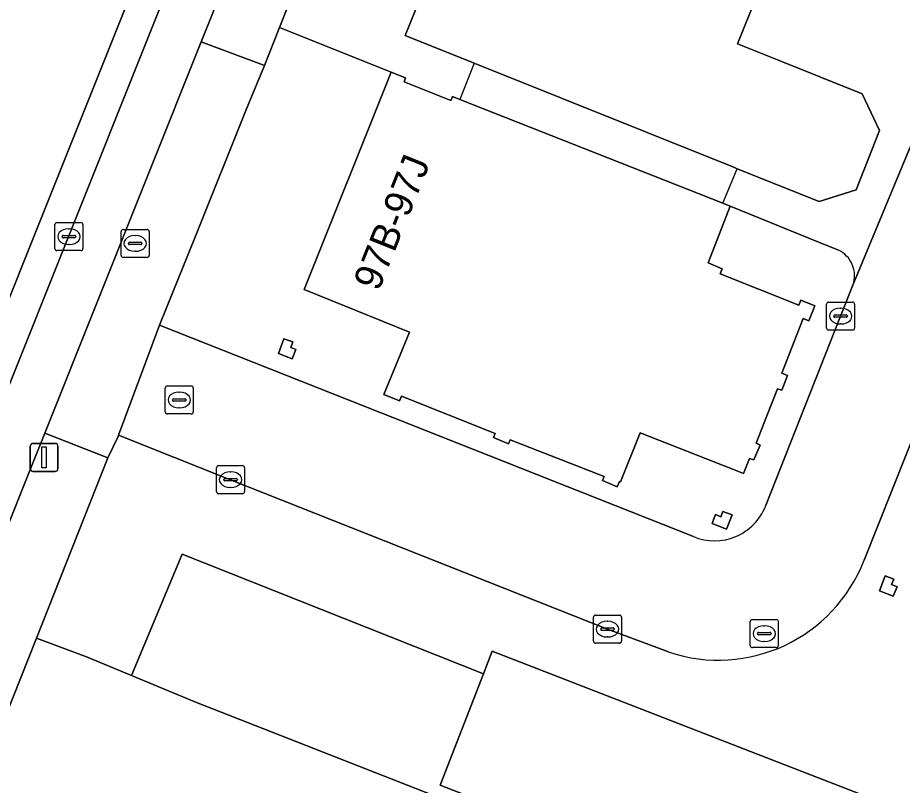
# Model space of a CAD drawing. Extents: x 160023 to 161302, y 384750 to 385707.
# Drawn here: x 160406.94 to 160438.47, y 384923.61 to 384950.96 of the extents above; entities that cross this region are included whole.
import ezdxf

# ---------------------------------------------------------------- set-up
doc = ezdxf.new("R2010")
doc.units = 0
for name, color, linetype in [('IMGEO_Brandkraan', 7, 'Continuous'), ('IMGEO_Erf', 7, 'Continuous'), ('IMGEO_Groenvoorziening', 7, 'Continuous'), ('IMGEO_Kolk', 7, 'Continuous'), ('IMGEO_Lichtmast', 7, 'Continuous'), ('IMGEO_Pand', 7, 'Continuous'), ('IMGEO_Pand_nummerreeks', 7, 'Continuous'), ('IMGEO_Pand_overbouw', 7, 'Continuous'), ('IMGEO_Parkeervlak_open', 7, 'Continuous'), ('IMGEO_Rijbaan_lokaal_open', 7, 'Continuous'), ('IMGEO_Rioolput', 7, 'Continuous'), ('IMGEO_Voetpad_open', 7, 'Continuous')]:
    doc.layers.add(name, color=color, linetype=linetype)

msp = doc.modelspace()

# ---------------------------------------------------------------- linework, layer by layer
at = {"layer": 'IMGEO_Brandkraan'}
for p, q in [((160410.7, 384943.415), (160411.552, 384943.415)), ((160410.625, 384942.489), (160410.625, 384943.341)), ((160411.113, 384943.195), (160411.138, 384943.195)), ((160411.626, 384943.341), (160411.626, 384942.489)), ((160410.884, 384942.909), (160410.884, 384942.921)), ((160411.322, 384942.872), (160410.924, 384942.872)), ((160410.927, 384942.958), (160411.325, 384942.958)), ((160411.368, 384942.921), (160411.368, 384942.909)), ((160411.136, 384942.635), (160411.111, 384942.635)), ((160411.552, 384942.415), (160410.7, 384942.415))]:
    msp.add_line(p, q, dxfattribs=at)
for points in [[(160410.7, 384943.415), (160411.552, 384943.415)], [(160410.625, 384942.489), (160410.625, 384943.341)], [(160411.626, 384943.341), (160411.626, 384942.489)], [(160411.552, 384942.415), (160410.7, 384942.415)]]:
    msp.add_lwpolyline(points, dxfattribs=at)
for centre, radius, start, end in [((160410.702, 384943.339), 0.0765, 91.552, 178.448), ((160410.702, 384943.339), 0.0765, 91.552, 178.448), ((160411.55, 384943.339), 0.0765, 1.552, 88.448), ((160411.55, 384943.339), 0.0765, 1.552, 88.448), ((160410.924, 384942.918), 0.0403, 85.8775, 175.7526), ((160410.921, 384942.908), 0.0366, 178.938, 274.7102), ((160411.325, 384942.915), 0.043, 264.8664, 352.4533), ((160411.329, 384942.92), 0.0386, 1.7309, 96.639), ((160410.702, 384942.491), 0.0765, 181.552, 268.448), ((160410.702, 384942.491), 0.0765, 181.552, 268.448), ((160411.55, 384942.491), 0.0765, 271.552, 358.448), ((160411.55, 384942.491), 0.0765, 271.552, 358.448)]:
    msp.add_arc(centre, radius, start, end, dxfattribs=at)
for centre, major_axis, ratio, start_param, end_param in [((160411.112, 384942.915), (-0.387, 0.002), 0.722429, 4.712389, 7.853982), ((160411.137, 384942.915), (-0.39, 0.002), 0.717154, 1.570796, 4.712389)]:
    msp.add_ellipse(centre, major_axis=major_axis, ratio=ratio, start_param=start_param, end_param=end_param, dxfattribs=at)
at = {"layer": 'IMGEO_Erf'}
for points in [[(160458.726, 385056.493), (160441.331, 385013.476), (160438.559, 385006.481), (160435.95, 385000), (160433.025, 384992.731), (160431.128, 384987.859), (160426.923, 384977.317), (160416.629, 384951.506), (160416.272, 384950.612), (160420.254, 384949.022), (160420.765, 384948.818), (160420.709, 384948.678), (160422.38, 384948.009), (160422.436, 384948.148), (160422.695, 384948.044), (160432.074, 384944.348), (160432.335, 384944.246), (160435.835, 384942.822), (160436.171, 384942.686)], [(160436.706, 384941.424), (160440.25, 384949.977), (160441.262, 384952.523), (160445.036, 384951.023), (160445.638, 384950.784), (160446.817, 384953.749), (160447.923, 384956.534), (160449.032, 384959.325), (160450.141, 384962.114), (160451.224, 384964.839), (160452.307, 384967.562), (160454.73, 384973.66), (160460.672, 384972.123)], [(160433.72, 384952.825), (160432.596, 384950.023), (160434.018, 384949.453), (160437.039, 384948.242), (160437.65, 384946.942), (160436.826, 384944.822), (160435.502, 384944.407), (160432.582, 384945.577), (160432.481, 384945.618), (160423.213, 384949.334), (160420.753, 384950.32), (160421.129, 384951.258)]]:
    msp.add_lwpolyline(points, dxfattribs=at)
msp.add_arc((160435.751, 384941.763), 1.014, 340.4385, 65.5086, dxfattribs=at)
at = {"layer": 'IMGEO_Groenvoorziening'}
for points in [[(160420.254, 384949.022), (160416.272, 384950.612), (160415.733, 384949.26), (160415.154, 384947.855), (160415.072, 384947.651), (160413.273, 384943.178), (160412.245, 384940.619), (160411.995, 384939.997), (160431.023, 384932.47)], [(160436.171, 384942.686), (160435.835, 384942.822), (160432.335, 384944.246), (160431.544, 384942.219), (160432.044, 384942.01), (160431.981, 384941.837), (160434.778, 384940.719), (160434.851, 384940.897), (160435.344, 384940.695), (160435.137, 384940.159), (160434.938, 384940.244), (160434.426, 384938.934), (160434.176, 384938.288), (160434.374, 384938.214), (160434.168, 384937.681), (160434.02, 384937.733), (160433.638, 384936.772), (160433.253, 384935.796), (160433.395, 384935.73), (160433.177, 384935.202), (160433.022, 384935.253), (160432.808, 384934.714), (160432.449, 384934.856), (160429.128, 384936.17), (160428.423, 384934.418), (160428.393, 384934.429), (160428.31, 384934.246), (160427.778, 384934.462), (160427.838, 384934.611), (160424.491, 384935.921), (160424.427, 384935.774), (160423.891, 384935.995), (160423.951, 384936.143), (160420.616, 384937.475), (160420.543, 384937.304), (160419.988, 384937.532), (160420.901, 384939.752), (160417.15, 384941.279), (160420.254, 384949.022)], [(160442.437, 384945.142), (160440.178, 384939.33), (160437.102, 384931.63)], [(160433.589, 384933.547), (160436.267, 384940.325), (160436.706, 384941.424)], [(160430.132, 384928.359), (160427.959, 384929.171), (160414.526, 384934.496), (160410.538, 384936.086), (160410.52, 384936.037), (160410.154, 384935.27), (160407.607, 384928.852), (160409.395, 384928.189), (160411, 384927.518), (160412.807, 384931.842), (160423.538, 384927.577), (160423.855, 384928.392), (160434.063, 384924.423), (160439.671, 384922.243), (160439.312, 384921.321), (160442.044, 384920.242), (160468.993, 384909.67)]]:
    msp.add_lwpolyline(points, dxfattribs=at)
for points in [[(160416.749, 384939.405), (160416.676, 384939.211), (160416.857, 384939.14), (160416.721, 384938.807), (160416.235, 384938.998), (160416.419, 384939.519)], [(160431.997, 384933.176), (160432.071, 384933.362), (160432.4, 384933.243), (160432.197, 384932.731), (160431.686, 384932.934), (160431.811, 384933.25)], [(160438.138, 384930.34), (160437.649, 384930.535), (160437.85, 384931.068), (160438.162, 384930.953), (160438.085, 384930.759), (160438.28, 384930.684)]]:
    msp.add_lwpolyline(points, close=True, dxfattribs=at)
for centre, radius, start, end in [((160435.751, 384941.763), 1.014, 340.4385, 65.5086), ((160431.774, 384934.275), 1.955, 247.4073, 338.1302), ((160431.913, 384933.624), 5.559, 251.3079, 338.9732)]:
    msp.add_arc(centre, radius, start, end, dxfattribs=at)
at = {"layer": 'IMGEO_Kolk'}
for p, q in [((160408.265, 384942.732), (160408.265, 384943.584)), ((160408.34, 384943.658), (160409.192, 384943.658)), ((160408.753, 384943.438), (160408.778, 384943.438)), ((160409.266, 384943.584), (160409.266, 384942.732)), ((160408.524, 384943.152), (160408.524, 384943.164)), ((160408.962, 384943.115), (160408.564, 384943.115)), ((160408.567, 384943.201), (160408.965, 384943.201)), ((160409.008, 384943.164), (160409.008, 384943.152)), ((160408.776, 384942.878), (160408.751, 384942.878)), ((160409.192, 384942.658), (160408.34, 384942.658)), ((160435.766, 384939.899), (160435.766, 384940.751)), ((160435.841, 384940.825), (160436.693, 384940.825)), ((160436.254, 384940.605), (160436.279, 384940.605)), ((160436.767, 384940.751), (160436.767, 384939.899)), ((160436.025, 384940.319), (160436.025, 384940.331)), ((160436.463, 384940.282), (160436.065, 384940.282)), ((160436.068, 384940.368), (160436.466, 384940.368)), ((160436.509, 384940.331), (160436.509, 384940.319)), ((160436.277, 384940.045), (160436.252, 384940.045)), ((160436.693, 384939.825), (160435.841, 384939.825)), ((160414.025, 384934.07), (160414.025, 384934.922)), ((160414.1, 384934.996), (160414.952, 384934.996)), ((160415.026, 384934.922), (160415.026, 384934.07)), ((160414.513, 384934.776), (160414.538, 384934.776)), ((160414.284, 384934.49), (160414.284, 384934.502)), ((160414.722, 384934.453), (160414.324, 384934.453)), ((160414.327, 384934.539), (160414.725, 384934.539)), ((160414.768, 384934.502), (160414.768, 384934.49)), ((160414.952, 384933.996), (160414.1, 384933.996)), ((160414.536, 384934.216), (160414.511, 384934.216)), ((160427.458, 384928.745), (160427.458, 384929.597)), ((160427.533, 384929.671), (160428.385, 384929.671)), ((160428.459, 384929.597), (160428.459, 384928.745)), ((160427.946, 384929.451), (160427.971, 384929.451)), ((160427.717, 384929.165), (160427.717, 384929.177)), ((160428.155, 384929.128), (160427.757, 384929.128)), ((160427.76, 384929.214), (160428.158, 384929.214)), ((160428.201, 384929.177), (160428.201, 384929.165)), ((160428.385, 384928.671), (160427.533, 384928.671)), ((160427.969, 384928.891), (160427.944, 384928.891))]:
    msp.add_line(p, q, dxfattribs=at)
for points in [[(160408.265, 384942.732), (160408.265, 384943.584)], [(160408.34, 384943.658), (160409.192, 384943.658)], [(160409.266, 384943.584), (160409.266, 384942.732)], [(160409.192, 384942.658), (160408.34, 384942.658)], [(160435.766, 384939.899), (160435.766, 384940.751)], [(160435.841, 384940.825), (160436.693, 384940.825)], [(160436.767, 384940.751), (160436.767, 384939.899)], [(160436.693, 384939.825), (160435.841, 384939.825)], [(160414.025, 384934.07), (160414.025, 384934.922)], [(160414.1, 384934.996), (160414.952, 384934.996)], [(160415.026, 384934.922), (160415.026, 384934.07)], [(160414.952, 384933.996), (160414.1, 384933.996)], [(160427.458, 384928.745), (160427.458, 384929.597)], [(160427.533, 384929.671), (160428.385, 384929.671)], [(160428.459, 384929.597), (160428.459, 384928.745)], [(160428.385, 384928.671), (160427.533, 384928.671)]]:
    msp.add_lwpolyline(points, dxfattribs=at)
for centre, radius, start, end in [((160408.342, 384943.582), 0.0765, 91.552, 178.448), ((160408.342, 384943.582), 0.0765, 91.552, 178.448), ((160409.19, 384943.582), 0.0765, 1.552, 88.448), ((160409.19, 384943.582), 0.0765, 1.552, 88.448), ((160408.564, 384943.161), 0.0403, 85.8775, 175.7526), ((160408.561, 384943.151), 0.0366, 178.938, 274.7102), ((160408.965, 384943.158), 0.043, 264.8664, 352.4533), ((160408.969, 384943.163), 0.0386, 1.7309, 96.639), ((160408.342, 384942.734), 0.0765, 181.552, 268.448), ((160408.342, 384942.734), 0.0765, 181.552, 268.448), ((160409.19, 384942.734), 0.0765, 271.552, 358.448), ((160409.19, 384942.734), 0.0765, 271.552, 358.448), ((160435.843, 384940.749), 0.0765, 91.552, 178.448), ((160435.843, 384940.749), 0.0765, 91.552, 178.448), ((160436.691, 384940.749), 0.0765, 1.552, 88.448), ((160436.691, 384940.749), 0.0765, 1.552, 88.448), ((160436.065, 384940.328), 0.0403, 85.8775, 175.7526), ((160436.062, 384940.318), 0.0366, 178.938, 274.7102), ((160436.466, 384940.325), 0.043, 264.8664, 352.4533), ((160436.47, 384940.33), 0.0386, 1.7309, 96.639), ((160435.843, 384939.901), 0.0765, 181.552, 268.448), ((160435.843, 384939.901), 0.0765, 181.552, 268.448), ((160436.691, 384939.901), 0.0765, 271.552, 358.448), ((160436.691, 384939.901), 0.0765, 271.552, 358.448), ((160414.102, 384934.92), 0.0765, 91.552, 178.448), ((160414.102, 384934.92), 0.0765, 91.552, 178.448), ((160414.95, 384934.92), 0.0765, 1.552, 88.448), ((160414.95, 384934.92), 0.0765, 1.552, 88.448), ((160414.324, 384934.499), 0.0403, 85.8775, 175.7526), ((160414.321, 384934.489), 0.0366, 178.938, 274.7102), ((160414.725, 384934.496), 0.043, 264.8664, 352.4533), ((160414.729, 384934.501), 0.0386, 1.7309, 96.639), ((160414.102, 384934.072), 0.0765, 181.552, 268.448), ((160414.102, 384934.072), 0.0765, 181.552, 268.448), ((160414.95, 384934.072), 0.0765, 271.552, 358.448), ((160414.95, 384934.072), 0.0765, 271.552, 358.448), ((160427.535, 384929.595), 0.0765, 91.552, 178.448), ((160427.535, 384929.595), 0.0765, 91.552, 178.448), ((160428.383, 384929.595), 0.0765, 1.552, 88.448), ((160428.383, 384929.595), 0.0765, 1.552, 88.448), ((160427.757, 384929.174), 0.0403, 85.8775, 175.7526), ((160427.754, 384929.164), 0.0366, 178.938, 274.7102), ((160428.158, 384929.171), 0.043, 264.8664, 352.4533), ((160428.162, 384929.176), 0.0386, 1.7309, 96.639), ((160427.535, 384928.747), 0.0765, 181.552, 268.448), ((160427.535, 384928.747), 0.0765, 181.552, 268.448), ((160428.383, 384928.747), 0.0765, 271.552, 358.448), ((160428.383, 384928.747), 0.0765, 271.552, 358.448)]:
    msp.add_arc(centre, radius, start, end, dxfattribs=at)
for centre, major_axis, ratio, start_param, end_param in [((160408.752, 384943.158), (-0.387, 0.002), 0.722429, 4.712389, 7.853982), ((160408.777, 384943.158), (-0.39, 0.002), 0.717154, 1.570796, 4.712389), ((160436.253, 384940.325), (-0.387, 0.002), 0.722429, 4.712389, 7.853982), ((160436.278, 384940.325), (-0.39, 0.002), 0.717154, 1.570796, 4.712389), ((160414.512, 384934.496), (-0.387, 0.002), 0.722429, 4.712389, 7.853982), ((160414.537, 384934.496), (-0.39, 0.002), 0.717154, 1.570796, 4.712389), ((160427.945, 384929.171), (-0.387, 0.002), 0.722429, 4.712389, 7.853982), ((160427.97, 384929.171), (-0.39, 0.002), 0.717154, 1.570796, 4.712389)]:
    msp.add_ellipse(centre, major_axis=major_axis, ratio=ratio, start_param=start_param, end_param=end_param, dxfattribs=at)
at = {"layer": 'IMGEO_Lichtmast'}
for p, q in [((160407.385, 384934.888), (160407.385, 384935.688)), ((160407.385, 384935.688), (160407.385, 384934.888)), ((160407.485, 384935.788), (160408.275, 384935.788)), ((160408.275, 384935.788), (160407.485, 384935.788)), ((160408.375, 384935.688), (160408.375, 384934.888)), ((160408.375, 384934.888), (160408.375, 384935.688)), ((160408.275, 384934.788), (160407.485, 384934.788)), ((160407.485, 384934.788), (160408.275, 384934.788))]:
    msp.add_line(p, q, dxfattribs=at)
msp.add_lwpolyline([(160407.805, 384935.663), (160407.955, 384935.663), (160407.955, 384934.913), (160407.805, 384934.913), (160407.805, 384935.663)], dxfattribs=at)
for centre, start, end in [((160407.485, 384935.688), 90, 180), ((160407.485, 384935.688), 90, 180), ((160408.275, 384935.688), 0, 90), ((160408.275, 384935.688), 360, 90), ((160407.485, 384934.888), 180, 270), ((160407.485, 384934.888), 180, 270), ((160408.275, 384934.888), 270, 0), ((160408.275, 384934.888), 270, 0)]:
    msp.add_arc(centre, 0.1, start, end, dxfattribs=at)
at = {"layer": 'IMGEO_Pand'}
for points in [[(160433.72, 384952.825), (160431.518, 384953.709), (160431.415, 384953.452), (160423.741, 384956.532), (160423.845, 384956.791), (160423.34, 384956.993), (160421.864, 384953.313), (160421.394, 384953.502), (160420.582, 384951.477), (160421.129, 384951.258), (160420.753, 384950.32), (160423.213, 384949.334), (160432.481, 384945.618), (160432.582, 384945.577), (160435.502, 384944.407), (160436.826, 384944.822), (160437.65, 384946.942), (160437.039, 384948.242), (160434.018, 384949.453), (160432.596, 384950.023)], [(160432.335, 384944.246), (160432.074, 384944.348), (160422.695, 384948.044), (160422.436, 384948.148), (160422.38, 384948.009), (160420.709, 384948.678), (160420.765, 384948.818), (160420.254, 384949.022), (160417.15, 384941.279), (160420.901, 384939.752), (160419.988, 384937.532), (160420.543, 384937.304), (160420.616, 384937.475), (160423.951, 384936.143), (160423.891, 384935.995), (160424.427, 384935.774), (160424.491, 384935.921), (160427.838, 384934.611), (160427.778, 384934.462), (160428.31, 384934.246), (160428.393, 384934.429), (160428.423, 384934.418), (160429.128, 384936.17), (160432.449, 384934.856), (160432.808, 384934.714), (160433.022, 384935.253), (160433.177, 384935.202), (160433.395, 384935.73), (160433.253, 384935.796), (160433.638, 384936.772), (160434.02, 384937.733), (160434.168, 384937.681), (160434.374, 384938.214), (160434.176, 384938.288), (160434.426, 384938.934), (160434.938, 384940.244), (160435.137, 384940.159), (160435.344, 384940.695), (160434.851, 384940.897), (160434.778, 384940.719), (160431.981, 384941.837), (160432.044, 384942.01), (160431.544, 384942.219)], [(160416.749, 384939.405), (160416.419, 384939.519), (160416.235, 384938.998), (160416.721, 384938.807), (160416.857, 384939.14), (160416.676, 384939.211)], [(160432.4, 384933.243), (160432.071, 384933.362), (160431.997, 384933.176), (160431.811, 384933.25), (160431.686, 384932.934), (160432.197, 384932.731)], [(160438.085, 384930.759), (160438.162, 384930.953), (160437.85, 384931.068), (160437.649, 384930.535), (160438.138, 384930.34), (160438.28, 384930.684)], [(160439.312, 384921.321), (160439.671, 384922.243), (160434.063, 384924.423), (160423.855, 384928.392), (160423.538, 384927.577), (160421.997, 384923.615), (160432.261, 384919.624), (160437.813, 384917.466)]]:
    msp.add_lwpolyline(points, close=True, dxfattribs=at)
at = {"layer": 'IMGEO_Pand_overbouw'}
msp.add_lwpolyline([(160423.213, 384949.334), (160422.695, 384948.044), (160432.074, 384944.348), (160432.582, 384945.577), (160432.481, 384945.618)], close=True, dxfattribs=at)
at = {"layer": 'IMGEO_Parkeervlak_open'}
for points in [[(160434.346, 385007.194), (160431.47, 385000), (160386.339, 384887.1), (160382.619, 384876.93)], [(160400.371, 384917.283), (160402.889, 384923.544), (160405.435, 384929.996), (160407.425, 384934.937), (160407.909, 384936.149), (160413.481, 384950.096), (160414.395, 384952.383), (160424.716, 384978.214), (160428.955, 384988.826), (160430.829, 384993.516), (160433.421, 385000), (160435.044, 385004.062)]]:
    msp.add_lwpolyline(points, dxfattribs=at)
msp.add_lwpolyline([(160423.538, 384927.577), (160412.807, 384931.842), (160411, 384927.518), (160413.25, 384926.578), (160446.36, 384913.598), (160465.64, 384906.014), (160467.26, 384905.381), (160468.993, 384909.67), (160442.044, 384920.242), (160439.312, 384921.321), (160437.813, 384917.466), (160432.261, 384919.624), (160421.997, 384923.615)], close=True, dxfattribs=at)
at = {"layer": 'IMGEO_Rijbaan_lokaal_open'}
msp.add_lwpolyline([(160430.241, 385000), (160436.681, 385016.096), (160448.949, 385047.038), (160444.248, 385048.841), (160424.752, 385000), (160388.819, 384909.958), (160385.618, 384898.566), (160385.418, 384898), (160388.913, 384896.667)], close=True, dxfattribs=at)
for points in [[(160431.47, 385000), (160434.346, 385007.194), (160434.727, 385008.141), (160437.516, 385015.078), (160437.787, 385015.747), (160450.033, 385046.622), (160448.949, 385047.038), (160436.681, 385016.096), (160430.241, 385000), (160388.913, 384896.667), (160386.013, 384889.416), (160385.258, 384887.528)], [(160380.216, 384869.227), (160382.619, 384876.93), (160386.339, 384887.1), (160431.47, 385000)], [(160467.118, 384968.668), (160460.376, 384971.378), (160457.966, 384965.313), (160456.883, 384962.59), (160455.8, 384959.865), (160454.691, 384957.075), (160453.582, 384954.285), (160452.476, 384951.501), (160451.298, 384948.538), (160445.638, 384950.784), (160445.036, 384951.023), (160444.025, 384948.477), (160440.25, 384949.977), (160436.706, 384941.424), (160436.267, 384940.325), (160433.589, 384933.547)], [(160437.102, 384931.63), (160440.178, 384939.33), (160442.437, 384945.142)], [(160431.023, 384932.47), (160411.995, 384939.997), (160410.538, 384936.086), (160414.526, 384934.496), (160427.959, 384929.171), (160430.132, 384928.359)], [(160446.36, 384913.598), (160413.25, 384926.578), (160411, 384927.518), (160409.395, 384928.189), (160407.607, 384928.852), (160405.361, 384923.214), (160407.138, 384922.439), (160408.748, 384921.809), (160410.911, 384920.963), (160424.604, 384915.668), (160425.099, 384915.491)]]:
    msp.add_lwpolyline(points, dxfattribs=at)
for centre, radius, start, end in [((160431.774, 384934.275), 1.955, 247.4073, 338.1302), ((160431.913, 384933.624), 5.559, 251.3079, 338.9732)]:
    msp.add_arc(centre, radius, start, end, dxfattribs=at)
at = {"layer": 'IMGEO_Rioolput'}
for p, q in [((160412.197, 384936.911), (160412.197, 384937.763)), ((160412.272, 384937.837), (160413.124, 384937.837)), ((160413.198, 384937.763), (160413.198, 384936.911)), ((160412.685, 384937.617), (160412.71, 384937.617)), ((160412.456, 384937.331), (160412.456, 384937.343)), ((160412.894, 384937.294), (160412.496, 384937.294)), ((160412.499, 384937.38), (160412.897, 384937.38)), ((160412.94, 384937.343), (160412.94, 384937.331)), ((160413.124, 384936.837), (160412.272, 384936.837)), ((160412.708, 384937.057), (160412.683, 384937.057)), ((160433.047, 384928.586), (160433.047, 384929.438)), ((160433.122, 384929.512), (160433.974, 384929.512)), ((160433.535, 384929.292), (160433.56, 384929.292)), ((160434.048, 384929.438), (160434.048, 384928.586)), ((160433.306, 384929.006), (160433.306, 384929.018)), ((160433.744, 384928.969), (160433.346, 384928.969)), ((160433.349, 384929.055), (160433.747, 384929.055)), ((160433.79, 384929.018), (160433.79, 384929.006)), ((160433.558, 384928.732), (160433.533, 384928.732)), ((160433.974, 384928.512), (160433.122, 384928.512))]:
    msp.add_line(p, q, dxfattribs=at)
for points in [[(160412.197, 384936.911), (160412.197, 384937.763)], [(160412.272, 384937.837), (160413.124, 384937.837)], [(160413.198, 384937.763), (160413.198, 384936.911)], [(160413.124, 384936.837), (160412.272, 384936.837)], [(160433.047, 384928.586), (160433.047, 384929.438)], [(160433.122, 384929.512), (160433.974, 384929.512)], [(160434.048, 384929.438), (160434.048, 384928.586)], [(160433.974, 384928.512), (160433.122, 384928.512)]]:
    msp.add_lwpolyline(points, dxfattribs=at)
for centre, radius, start, end in [((160412.274, 384937.761), 0.0765, 91.552, 178.448), ((160412.274, 384937.761), 0.0765, 91.552, 178.448), ((160413.122, 384937.761), 0.0765, 1.552, 88.448), ((160413.122, 384937.761), 0.0765, 1.552, 88.448), ((160412.496, 384937.34), 0.0403, 85.8775, 175.7526), ((160412.493, 384937.33), 0.0366, 178.938, 274.7102), ((160412.897, 384937.337), 0.043, 264.8664, 352.4533), ((160412.901, 384937.342), 0.0386, 1.7309, 96.639), ((160412.274, 384936.913), 0.0765, 181.552, 268.448), ((160412.274, 384936.913), 0.0765, 181.552, 268.448), ((160413.122, 384936.913), 0.0765, 271.552, 358.448), ((160413.122, 384936.913), 0.0765, 271.552, 358.448), ((160433.124, 384929.436), 0.0765, 91.552, 178.448), ((160433.124, 384929.436), 0.0765, 91.552, 178.448), ((160433.972, 384929.436), 0.0765, 1.552, 88.448), ((160433.972, 384929.436), 0.0765, 1.552, 88.448), ((160433.346, 384929.015), 0.0403, 85.8775, 175.7526), ((160433.343, 384929.005), 0.0366, 178.938, 274.7102), ((160433.747, 384929.012), 0.043, 264.8664, 352.4533), ((160433.751, 384929.017), 0.0386, 1.7309, 96.639), ((160433.124, 384928.588), 0.0765, 181.552, 268.448), ((160433.124, 384928.588), 0.0765, 181.552, 268.448), ((160433.972, 384928.588), 0.0765, 271.552, 358.448), ((160433.972, 384928.588), 0.0765, 271.552, 358.448)]:
    msp.add_arc(centre, radius, start, end, dxfattribs=at)
for centre, major_axis, ratio, start_param, end_param in [((160412.684, 384937.337), (-0.387, 0.002), 0.722429, 4.712389, 7.853982), ((160412.709, 384937.337), (-0.39, 0.002), 0.717154, 1.570796, 4.712389), ((160433.534, 384929.012), (-0.387, 0.002), 0.722429, 4.712389, 7.853982), ((160433.559, 384929.012), (-0.39, 0.002), 0.717154, 1.570796, 4.712389)]:
    msp.add_ellipse(centre, major_axis=major_axis, ratio=ratio, start_param=start_param, end_param=end_param, dxfattribs=at)
at = {"layer": 'IMGEO_Voetpad_open'}
for points in [[(160426.923, 384977.317), (160431.128, 384987.859), (160428.955, 384988.826), (160424.716, 384978.214), (160414.395, 384952.383), (160413.481, 384950.096), (160415.733, 384949.26), (160416.272, 384950.612), (160416.629, 384951.506)], [(160413.273, 384943.178), (160415.072, 384947.651), (160415.154, 384947.855), (160415.733, 384949.26), (160413.481, 384950.096), (160407.909, 384936.149), (160410.154, 384935.27), (160410.52, 384936.037), (160410.538, 384936.086), (160411.995, 384939.997), (160412.245, 384940.619)]]:
    msp.add_lwpolyline(points, close=True, dxfattribs=at)
msp.add_lwpolyline([(160403.358, 384918.197), (160404.882, 384922.015), (160405.361, 384923.214), (160407.607, 384928.852), (160410.154, 384935.27), (160407.909, 384936.149), (160407.425, 384934.937), (160405.435, 384929.996), (160405.9, 384929.813), (160403.354, 384923.361), (160402.889, 384923.544), (160400.371, 384917.283)], dxfattribs=at)

# ---------------------------------------------------------------- texts
at = {"layer": 'IMGEO_Pand_nummerreeks'}
msp.add_text('97B-97J', height=1, rotation=68.1533, dxfattribs=at).set_placement((160419.804, 384941.179))

doc.saveas('drawing.dxf')
